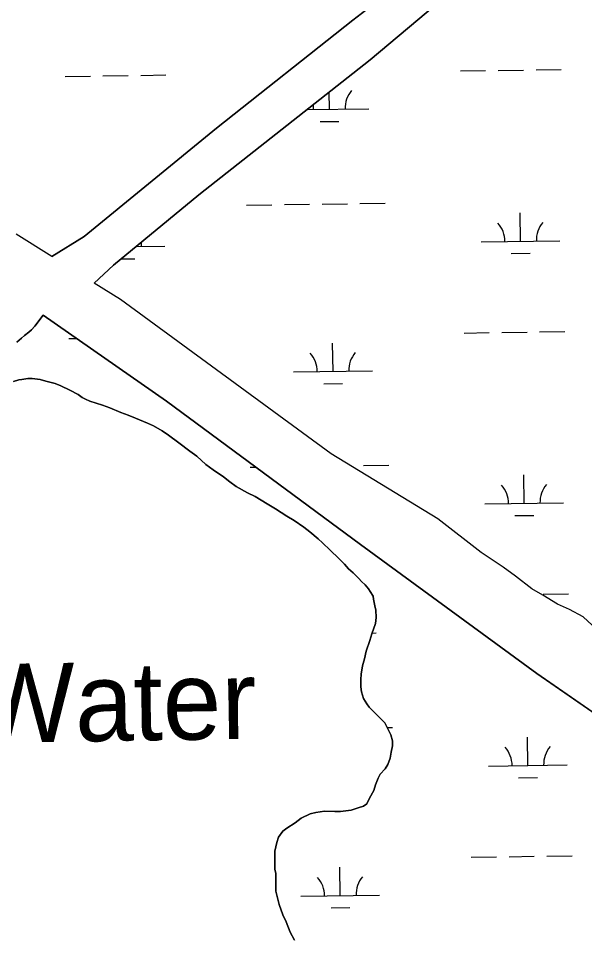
# Model space of a CAD drawing. Extents: x 3767014 to 3805179, y 361544 to 387384.
# Drawn here: x 3772343 to 3773062, y 381465 to 382629 of the extents above; entities that cross this region are included whole.
import ezdxf

# ---------------------------------------------------------------- set-up
doc = ezdxf.new("R2010")
doc.units = 0
for name, color, linetype in [('V-RIVR-IDEN', 7, 'Continuous'), ('V-TOPO-SHOR', 7, 'Continuous'), ('V-WETL-SWMP', 7, 'Continuous')]:
    doc.layers.add(name, color=color, linetype=linetype)

msp = doc.modelspace()

# ---------------------------------------------------------------- linework, layer by layer
at = {"layer": 'V-TOPO-SHOR'}
msp.add_line((3772385.208, 382326.994), (3772339.836, 382355.465), dxfattribs=at)
for points in [[(3772385.208, 382326.994), (3772426.344, 382352.309), (3772594.36, 382490.066), (3772767.651, 382627.03), (3772960.061, 382775.7), (3773037.066, 382843.592), (3773044.805, 382853.363), (3773049.929, 382862.216), (3773048.983, 382866.589), (3773014.892, 382914.301), (3772870.524, 383112.039), (3772685.83, 383363.534)], [(3773376.987, 382373.475), (3773316.962, 382452.358), (3773195.786, 382625.901), (3773079.05, 382796.004), (3773071.949, 382801.155), (3773065.783, 382802.812), (3773057.052, 382800.043), (3772981.704, 382738.318), (3772789.506, 382576.491), (3772572.01, 382405.494), (3772463.763, 382316.053), (3772438.951, 382293.267)], [(3773076.899, 381854.139), (3773059.852, 381869.6), (3773042.81, 381878.869), (3773027.319, 381885.816), (3773008.728, 381897.405), (3772994.787, 381905.128), (3772973.866, 381921.359), (3772958.371, 381932.95), (3772930.482, 381951.495), (3772875.47, 381994.003), (3772739.907, 382076.665), (3772472.305, 382272.337), (3772438.951, 382293.267)], [(3772374.167, 382252.778), (3772363.544, 382238.694), (3772359.462, 382234.019), (3772355.96, 382231.094), (3772350.711, 382227), (3772346.628, 382223.492), (3772340.795, 382218.229)], [(3774638.835, 380602.297), (3774635.73, 380609.26), (3774624.874, 380625.501), (3774571.401, 380675.753), (3774380.824, 380803.245), (3774203.406, 380932.3), (3774087.962, 381018.856), (3773888.083, 381157.946), (3773733.126, 381275.419), (3773493.739, 381438.459), (3773394.571, 381509.553), (3773149.738, 381695.034), (3773000.992, 381797.807), (3772777.086, 381961.639), (3772530.71, 382143.247), (3772374.167, 382252.778)], [(3772336.766, 382168.587), (3772343.189, 382170.346), (3772347.275, 382170.936), (3772354.865, 382172.114), (3772360.122, 382172.12), (3772370.632, 382170.965), (3772377.645, 382168.636), (3772389.326, 382165.73), (3772396.92, 382162.822), (3772408.023, 382157.577), (3772418.541, 382151.753), (3772423.8, 382148.255), (3772427.892, 382145.924), (3772433.733, 382143.595), (3772449.509, 382138.359), (3772458.856, 382134.867), (3772472.877, 382129.042), (3772482.226, 382125.55), (3772491.573, 382122.059), (3772506.763, 382115.652), (3772514.359, 382112.159), (3772525.463, 382105.748), (3772533.645, 382100.501), (3772546.502, 382090.591), (3772560.531, 382080.095), (3772569.298, 382073.683), (3772580.99, 382063.187), (3772590.342, 382056.191), (3772603.201, 382047.446), (3772611.383, 382041.034), (3772619.565, 382035.203), (3772633.589, 382027.044), (3772643.522, 382022.384), (3772658.718, 382013.06), (3772669.237, 382006.65), (3772683.847, 381997.323)], [(3772683.847, 381997.323), (3772693.196, 381992.078), (3772705.472, 381983.333), (3772713.068, 381977.505), (3772723.591, 381968.758), (3772728.854, 381963.509), (3772738.793, 381954.178), (3772749.899, 381943.68), (3772756.916, 381936.68), (3772762.177, 381930.847), (3772768.024, 381925.598), (3772775.04, 381918.598), (3772778.549, 381914.516), (3772783.226, 381910.435), (3772787.32, 381905.184), (3772789.659, 381901.682), (3772793.171, 381895.847), (3772793.759, 381892.343), (3772795.523, 381883.585), (3772796.696, 381878.332), (3772797.292, 381868.989), (3772796.133, 381861.395), (3772791.478, 381847.96), (3772789.151, 381839.781), (3772784.496, 381826.346), (3772782.172, 381816.413), (3772779.847, 381807.652), (3772778.106, 381797.139), (3772777.533, 381790.131), (3772777.543, 381780.786), (3772778.719, 381774.366), (3772781.066, 381766.192), (3772785.162, 381759.19), (3772788.086, 381755.106), (3772796.27, 381746.941), (3772800.948, 381742.273), (3772807.964, 381735.275), (3772811.476, 381728.271), (3772815.575, 381720.102), (3772817.919, 381712.514), (3772817.928, 381706.089), (3772816.185, 381697.912), (3772815.026, 381690.32), (3772812.117, 381682.14), (3772808.62, 381676.881), (3772802.203, 381669.864), (3772799.875, 381665.191), (3772796.381, 381656.425), (3772794.052, 381649.415), (3772788.809, 381639.482), (3772785.315, 381632.47), (3772781.23, 381629.545), (3772774.225, 381627.2), (3772765.47, 381624.272), (3772752.041, 381622.502), (3772744.45, 381622.494), (3772731.6, 381623.061), (3772720.508, 381621.298), (3772713.502, 381619.537), (3772701.831, 381614.265), (3772694.247, 381608.418), (3772683.743, 381601.398), (3772678.492, 381597.887), (3772673.245, 381590.289), (3772670.918, 381583.279), (3772668.596, 381572.181), (3772668.608, 381561.67), (3772668.622, 381549.405), (3772669.798, 381544.152), (3772669.804, 381538.897), (3772669.81, 381532.472), (3772669.824, 381521.378), (3772671.584, 381514.956), (3772673.933, 381504.447), (3772678.621, 381491.606), (3772682.719, 381482.851), (3772687.99, 381469.427), (3772693.258, 381459.506)]]:
    msp.add_lwpolyline(points, dxfattribs=at)
at = {"layer": 'V-WETL-SWMP'}
for p, q in [((3772960.06, 382775.7), (3772767.652, 382627.03)), ((3772767.652, 382627.03), (3772594.36, 382490.066)), ((3772402.25, 382555.63), (3772434.247, 382556.074)), ((3772450.245, 382556.297), (3772482.242, 382556.741)), ((3772498.241, 382556.963), (3772530.238, 382557.408)), ((3772904.109, 382562.601), (3772936.106, 382563.046)), ((3772952.105, 382563.268), (3772984.102, 382563.712)), ((3773000.1, 382563.935), (3773032.097, 382564.379)), ((3772737.706, 382513.855), (3772737.405, 382535.53)), ((3772709.336, 382513.461), (3772787.702, 382514.55)), ((3772725.922, 382498.259), (3772749.92, 382498.592)), ((3772594.36, 382490.066), (3772426.344, 382352.309)), ((3772632.54, 382392.312), (3772664.537, 382392.756)), ((3772680.536, 382392.978), (3772712.533, 382393.423)), ((3772728.531, 382393.645), (3772760.528, 382394.09)), ((3772776.527, 382394.312), (3772808.523, 382394.756)), ((3772980.528, 382346.399), (3772980.028, 382382.395)), ((3772385.207, 382326.994), (3772339.837, 382355.466)), ((3772426.344, 382352.309), (3772385.207, 382326.994)), ((3772930.533, 382345.704), (3773030.523, 382347.093)), ((3772492.28, 382339.616), (3772528.663, 382340.122)), ((3772473.283, 382323.92), (3772490.881, 382324.165)), ((3772968.743, 382330.803), (3772992.741, 382331.136)), ((3772363.544, 382238.695), (3772374.166, 382252.779)), ((3772374.166, 382252.779), (3772530.71, 382143.248)), ((3772350.711, 382227), (3772355.961, 382231.094)), ((3772355.961, 382231.094), (3772359.462, 382234.019)), ((3772359.462, 382234.019), (3772363.544, 382238.695)), ((3772908.73, 382229.958), (3772940.727, 382230.403)), ((3772956.726, 382230.625), (3772988.722, 382231.07)), ((3773004.721, 382231.292), (3773036.718, 382231.736)), ((3772340.794, 382218.229), (3772346.627, 382223.492)), ((3772346.627, 382223.492), (3772350.711, 382227)), ((3772406.871, 382222.987), (3772416.553, 382223.121)), ((3772742.327, 382181.212), (3772741.827, 382217.209)), ((3772692.332, 382180.518), (3772792.322, 382181.907)), ((3772343.188, 382170.347), (3772336.766, 382168.587)), ((3772347.275, 382170.936), (3772343.188, 382170.347)), ((3772354.865, 382172.113), (3772347.275, 382170.936)), ((3772360.121, 382172.119), (3772354.865, 382172.113)), ((3772370.633, 382170.964), (3772360.121, 382172.119)), ((3772377.644, 382168.637), (3772370.633, 382170.964)), ((3772389.326, 382165.731), (3772377.644, 382168.637)), ((3772396.921, 382162.821), (3772389.326, 382165.731)), ((3772408.023, 382157.578), (3772396.921, 382162.821)), ((3772418.541, 382151.752), (3772408.023, 382157.578)), ((3772730.543, 382165.616), (3772754.54, 382165.949)), ((3772423.801, 382148.254), (3772418.541, 382151.752)), ((3772427.892, 382145.923), (3772423.801, 382148.254)), ((3772433.734, 382143.595), (3772427.892, 382145.923)), ((3772449.508, 382138.358), (3772433.734, 382143.595)), ((3772458.855, 382134.866), (3772449.508, 382138.358)), ((3772472.877, 382129.043), (3772458.855, 382134.866)), ((3772530.71, 382143.248), (3772777.086, 381961.638)), ((3772482.225, 382125.55), (3772472.877, 382129.043)), ((3772491.573, 382122.058), (3772482.225, 382125.55)), ((3772506.763, 382115.653), (3772491.573, 382122.058)), ((3772514.359, 382112.158), (3772506.763, 382115.653)), ((3772525.462, 382105.748), (3772514.359, 382112.158)), ((3772533.644, 382100.502), (3772525.462, 382105.748)), ((3772546.503, 382090.591), (3772533.644, 382100.502)), ((3772560.531, 382080.096), (3772546.503, 382090.591)), ((3772569.298, 382073.683), (3772560.531, 382080.096)), ((3772580.99, 382063.186), (3772569.298, 382073.683)), ((3772590.342, 382056.19), (3772580.99, 382063.186)), ((3772603.2, 382047.446), (3772590.342, 382056.19)), ((3772637.161, 382059.669), (3772643.967, 382059.763)), ((3772764.87, 382061.443), (3772765.149, 382061.447)), ((3772781.147, 382061.669), (3772813.144, 382062.113)), ((3772611.383, 382041.033), (3772603.2, 382047.446)), ((3772619.565, 382035.203), (3772611.383, 382041.033)), ((3772985.149, 382013.756), (3772984.649, 382049.752)), ((3772633.59, 382027.044), (3772619.565, 382035.203)), ((3772643.523, 382022.385), (3772633.59, 382027.044)), ((3772658.718, 382013.06), (3772643.523, 382022.385)), ((3772669.237, 382006.649), (3772658.718, 382013.06)), ((3772683.847, 381997.323), (3772669.237, 382006.649)), ((3772935.153, 382013.061), (3773035.144, 382014.45)), ((3772693.197, 381992.079), (3772683.847, 381997.323)), ((3772973.364, 381998.16), (3772997.362, 381998.493)), ((3772705.471, 381983.334), (3772693.197, 381992.079)), ((3772713.069, 381977.504), (3772705.471, 381983.334)), ((3772723.591, 381968.757), (3772713.069, 381977.504)), ((3772728.853, 381963.508), (3772723.591, 381968.757)), ((3772738.792, 381954.177), (3772728.853, 381963.508)), ((3772777.086, 381961.638), (3773000.992, 381797.806)), ((3772749.9, 381943.679), (3772738.792, 381954.177)), ((3772756.916, 381936.68), (3772749.9, 381943.679)), ((3772762.178, 381930.847), (3772756.916, 381936.68)), ((3772768.024, 381925.598), (3772762.178, 381930.847)), ((3772775.04, 381918.599), (3772768.024, 381925.598)), ((3772778.549, 381914.516), (3772775.04, 381918.599)), ((3772783.226, 381910.434), (3772778.549, 381914.516)), ((3772787.32, 381905.183), (3772783.226, 381910.434)), ((3772789.66, 381901.682), (3772787.32, 381905.183)), ((3772793.171, 381895.847), (3772789.66, 381901.682)), ((3772793.759, 381892.343), (3772793.171, 381895.847)), ((3772795.522, 381883.586), (3772793.759, 381892.343)), ((3773009.342, 381898.649), (3773041.339, 381899.093)), ((3772796.696, 381878.332), (3772795.522, 381883.586)), ((3772797.291, 381868.989), (3772796.696, 381878.332)), ((3772796.132, 381861.396), (3772797.291, 381868.989)), ((3772791.477, 381847.96), (3772796.132, 381861.396)), ((3772789.151, 381839.781), (3772791.477, 381847.96)), ((3772791.904, 381849.194), (3772796.943, 381849.264)), ((3772784.496, 381826.345), (3772789.151, 381839.781)), ((3772782.172, 381816.414), (3772784.496, 381826.345)), ((3772779.847, 381807.652), (3772782.172, 381816.414)), ((3772777.532, 381790.131), (3772778.107, 381797.139)), ((3772778.107, 381797.139), (3772779.847, 381807.652)), ((3773000.992, 381797.806), (3773149.739, 381695.034)), ((3772777.543, 381780.787), (3772777.532, 381790.131)), ((3772778.719, 381774.365), (3772777.543, 381780.787)), ((3772781.065, 381766.192), (3772778.719, 381774.365)), ((3772785.161, 381759.19), (3772781.065, 381766.192)), ((3772788.086, 381755.106), (3772785.161, 381759.19)), ((3772796.271, 381746.94), (3772788.086, 381755.106)), ((3772800.948, 381742.274), (3772796.271, 381746.94)), ((3772807.964, 381735.275), (3772800.948, 381742.274)), ((3772811.477, 381728.272), (3772807.964, 381735.275)), ((3772810.923, 381729.376), (3772817.765, 381729.471)), ((3772815.574, 381720.101), (3772811.477, 381728.272)), ((3772817.919, 381712.513), (3772815.574, 381720.101)), ((3772989.769, 381681.113), (3772989.269, 381717.11)), ((3772816.185, 381697.912), (3772817.927, 381706.089)), ((3772817.927, 381706.089), (3772817.919, 381712.513)), ((3772815.026, 381690.319), (3772816.185, 381697.912)), ((3772808.619, 381676.88), (3772812.117, 381682.14)), ((3772812.117, 381682.14), (3772815.026, 381690.319)), ((3772939.774, 381680.419), (3773039.765, 381681.807)), ((3772799.874, 381665.19), (3772802.204, 381669.864)), ((3772802.204, 381669.864), (3772808.619, 381676.88)), ((3772796.381, 381656.426), (3772799.874, 381665.19)), ((3772977.985, 381665.517), (3773001.983, 381665.85)), ((3772788.81, 381639.482), (3772794.053, 381649.416)), ((3772794.053, 381649.416), (3772796.381, 381656.426)), ((3772785.315, 381632.47), (3772788.81, 381639.482)), ((3772720.508, 381621.297), (3772731.601, 381623.062)), ((3772731.601, 381623.062), (3772744.449, 381622.494)), ((3772744.449, 381622.494), (3772752.041, 381622.503)), ((3772752.041, 381622.503), (3772765.47, 381624.271)), ((3772765.47, 381624.271), (3772774.226, 381627.201)), ((3772774.226, 381627.201), (3772781.23, 381629.546)), ((3772781.23, 381629.546), (3772785.315, 381632.47)), ((3772694.246, 381608.418), (3772701.83, 381614.266)), ((3772701.83, 381614.266), (3772713.503, 381619.536)), ((3772713.503, 381619.536), (3772720.508, 381621.297)), ((3772678.491, 381597.887), (3772683.743, 381601.397)), ((3772683.743, 381601.397), (3772694.246, 381608.418)), ((3772670.918, 381583.279), (3772673.245, 381590.289)), ((3772673.245, 381590.289), (3772678.491, 381597.887)), ((3772668.595, 381572.181), (3772670.918, 381583.279)), ((3772668.608, 381561.67), (3772668.595, 381572.181)), ((3772917.972, 381564.673), (3772949.969, 381565.117)), ((3772965.967, 381565.339), (3772997.964, 381565.784)), ((3773013.963, 381566.006), (3773045.959, 381566.45)), ((3772668.623, 381549.406), (3772668.608, 381561.67)), ((3772669.797, 381544.152), (3772668.623, 381549.406)), ((3772669.804, 381538.897), (3772669.797, 381544.152)), ((3772751.569, 381515.926), (3772751.069, 381551.923)), ((3772669.811, 381532.473), (3772669.804, 381538.897)), ((3772669.825, 381521.378), (3772669.811, 381532.473)), ((3772671.584, 381514.956), (3772669.825, 381521.378)), ((3772673.933, 381504.448), (3772671.584, 381514.956)), ((3772701.574, 381515.232), (3772801.564, 381516.621)), ((3772678.62, 381491.606), (3772673.933, 381504.448)), ((3772739.784, 381500.33), (3772763.782, 381500.664)), ((3772682.719, 381482.852), (3772678.62, 381491.606)), ((3772687.991, 381469.427), (3772682.719, 381482.852)), ((3772693.258, 381459.506), (3772687.991, 381469.427))]:
    msp.add_line(p, q, dxfattribs=at)
msp.add_lwpolyline([(3773076.899, 381854.139), (3773059.851, 381869.6), (3773042.81, 381878.868), (3773027.32, 381885.816), (3773008.728, 381897.405), (3772994.786, 381905.129), (3772973.866, 381921.359), (3772958.371, 381932.951), (3772930.481, 381951.495), (3772875.471, 381994.003), (3772739.907, 382076.664), (3772472.305, 382272.336), (3772438.951, 382293.267), (3772463.763, 382316.054), (3772572.01, 382405.493), (3772789.506, 382576.492), (3772981.705, 382738.319), (3773057.053, 382800.042), (3773065.782, 382802.812)], dxfattribs=at)
for centre, start, end in [((3772792.937, 382515.097), 140.024034, 181.567693), ((3772682.462, 382513.563), 0.024037, 9.91224), ((3772925.284, 382346.106), 0.024037, 41.567696), ((3773035.759, 382347.641), 140.024034, 181.567693), ((3772533.899, 382340.669), 172.755306, 181.567693), ((3772687.083, 382180.92), 0.024037, 41.567696), ((3772797.558, 382182.454), 140.024034, 181.567693), ((3772929.904, 382013.463), 0.024037, 41.567696), ((3773040.38, 382014.998), 140.024034, 181.567693), ((3772934.525, 381680.82), 0.024037, 41.567696), ((3773045, 381682.355), 140.024034, 181.567693), ((3772696.325, 381515.634), 0.024037, 41.567696), ((3772806.8, 381517.169), 140.024034, 181.567693)]:
    msp.add_arc(centre, 35.246, start, end, dxfattribs=at)

# ---------------------------------------------------------------- texts
at = {"layer": 'V-RIVR-IDEN'}
msp.add_text('Water', height=100, rotation=0.919589, dxfattribs=at).set_placement((3772289.079, 381709.481))

doc.saveas('drawing.dxf')
